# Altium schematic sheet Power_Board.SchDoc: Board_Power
size A4; Date: Not used; ApprovedBy: Not used; CheckedBy: Not used; Author: Not used; CompanyName: STMicroelectronics; DrawnBy: Not used; Engineer: Not used; Organization: Not used; Address1: Not used; Address2: Not used; Address3: Not used; Address4: Not used; DocumentNumber: Not used; Revision: Not used; SheetNumber: 15; SheetTotal: 17
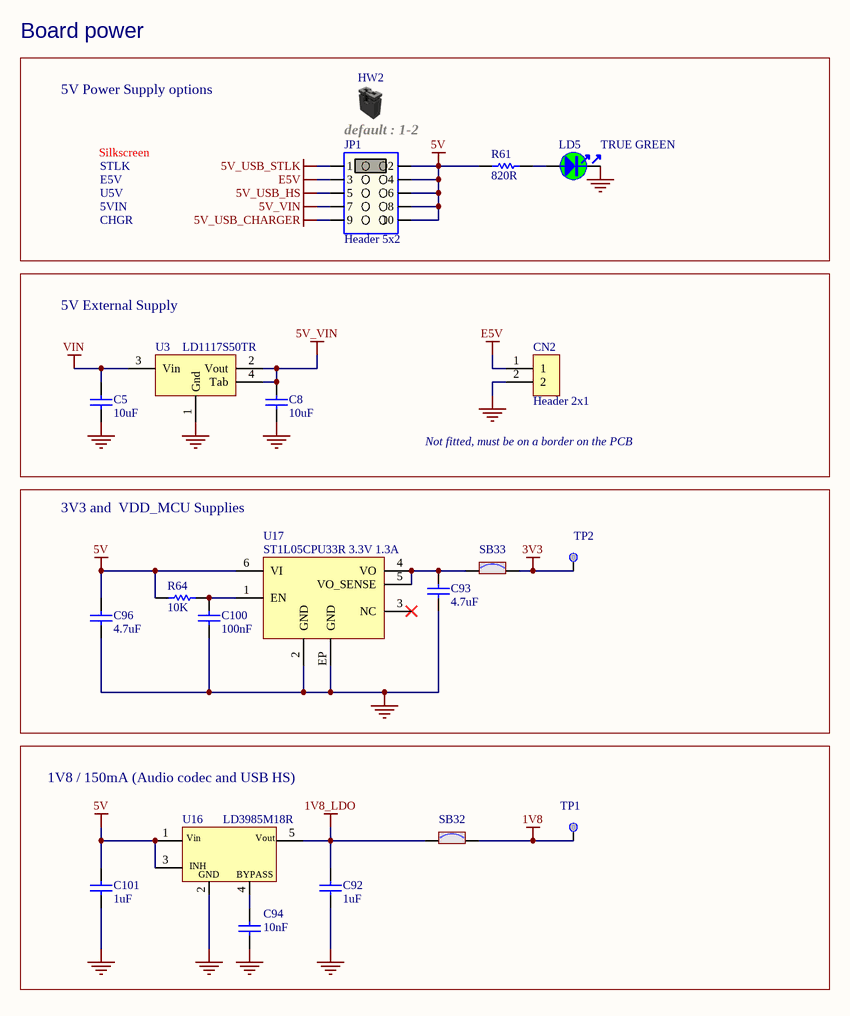
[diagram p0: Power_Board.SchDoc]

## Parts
C5  value 10uF  [C0805]  (hidden comment: Capacitor)
C8  value 10uF  [C0805]  (hidden comment: Capacitor)
C92  value 1uF  [C0402]  (hidden comment: Capacitor)
C93  value 4.7uF  [C0603]  (hidden comment: Capacitor)
C94  value 10nF  [C0402]  (hidden comment: Capacitor)
C96  value 4.7uF  [C0603]  (hidden comment: Capacitor)
C100  value 100nF  [C0402]  (hidden comment: Capacitor)
C101  value 1uF  [C0402]  (hidden comment: Capacitor)
CN2  Header 2x1  [CON_SAMTEC_TSW-102-07-G-S]
HW2  Shunt Black 2.54mm  (value not drawn)  (mechanical)
JP1  value Header 5x2  [CON_SAMTEC_TSM-105-01-L-DV]  (hidden comment: Jumper_Header 5x2 Fitted 1-2)
LD5  value TRUE GREEN  [LED_0603_VISHAY_VLMTG1300-GS08_GREEN_1A2K_H0P8]  (hidden comment: LED_green)
R61  value 820R  [R0603]  (hidden comment: Resistor)
R64  value 10K  [R0402]  (hidden comment: Resistor)
SB32  SB_ON  [SOLDER-BRIDGE_R0603-0R]  (value not drawn)
SB33  SB_ON  [SOLDER-BRIDGE_R0603-0R]  (value not drawn)
TP1  Test Point  [TP_SMD_2MM]  (value not drawn)  (no BOM)
TP2  Test Point  [TP_SMD_2MM]  (value not drawn)  (no BOM)
U3  LD1117S50TR  [REG_SOT223-TAB]
U16  LD3985M18R  [REG_SOT23-5L]
U17  value ST1L05CPU33R 3.3V 1.3A  [ICC_DFN6-EPAD_3X3_P095]  (hidden comment: ST1L05CPU33R)

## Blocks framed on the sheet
Board power: HW2 JP1 LD5 R61
5V External Supply: C5 C8 CN2 U3
3V3 and  VDD_MCU Supplies: C93 C96 C100 R64 SB33 TP2 U17
1V8 / 150mA (Audio codec and USB HS): C92 C94 C101 SB32 TP1 U16

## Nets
1V8: SB32.2 TP1.1
1V8_LDO: C92.2 SB32.1 U16.5(Vout)
3V3: SB33.2 TP2.1
5V: C96.2 C101.2 JP1.2 JP1.4 JP1.6 JP1.8 JP1.10 R61.1 R64.1 U16.1(Vin) U16.3(CE) U17.6(VI)
5V_USB_CHARGER: JP1.9
5V_USB_HS: JP1.5
5V_USB_STLK: JP1.1
5V_VIN: C8.2 JP1.7 U3.2(Vout) U3.4(Tab)
E5V: CN2.1 JP1.3
GND: C5.1 C8.1 C92.1 C93.1 C94.1 C96.1 C100.1 C101.1 CN2.2 LD5.2 U3.1(Gnd) U16.2(GND) U17.2(GND) U17.EP(GND)
VIN: C5.2 U3.3(Vin)
NetC93_2: C93.2 SB33.1 U17.4(VO) U17.5(VO_SENSE)
NetC94_2: C94.2 U16.4(BYPASS)
NetC100_2: C100.2 R64.2 U17.1(EN)
NetLD5_1: LD5.1 R61.2

Not connected (* = marked no-connect by the designer): U17 3(NC)*

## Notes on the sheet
- 5V Power Supply options
- Silkscreen
- default : 1-2
- STLK
- E5V
- U5V
- 5VIN
- CHGR
- Not fitted, must be on a border on the PCB

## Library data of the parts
C5 C8 = MCD-00014: Capacitor, MLCC, 10uF, 25V, X5R, 10%, 0805, T=0,85mm; Manufacturer_Part_Number: CC0805KRX5R8BB106; Manufacturer: YAGEO; Provided_By: SUBCO
C92 C101 = MCD-00095: Capacitor, MLCC, 1uF, 6V3, X5R, 10%, 0402, T=0,5mm; Manufacturer_Part_Number: GRM155R61E105KA12; Manufacturer: MURATA; Alternate_Manufacturer_Part_Number: GRM155R60J105KE19; Provided_By: SUBCO
C93 C96 = MCD-00009: Capacitor, MLCC, 4.7uF, 16V, X5R, 10%, 0603, T=0.8mm; Manufacturer_Part_Number: CC0603KRX5R7BB475; Manufacturer: YAGEO; Provided_By: SUBCO
C94 = MCD-00011: Capacitor, MLCC, 10nF, 16V, X7R, 10%, 0402, T=0.5mm; Manufacturer_Part_Number: CC0402KRX7R7BB103; Manufacturer: YAGEO; Provided_By: SUBCO
C100 = MCD-00006: Capacitor, MLCC, 100nF, 16V, X7R, 10%, 0402, T=0.5mm; Manufacturer_Part_Number: CC0402KRX7R7BB104; Manufacturer: YAGEO; Alternate_Manufacturer_Part_Number: GCM155R71C104KA55D; Alternate_Manufacturer: MURATA; Provided_By: SUBCO
CN2 = MCD-00032: Header, 2x1, 2,54mm, VR, TH, Height 5.84mm/2.54mm; Part_Type: Connector; Manufacturer_Part_Number: TSW-102-07-G-S; Manufacturer: SAMTEC; Alternate_Manufacturer_Part_Number: 313102S111116; Alternate_Manufacturer: JIUBABA; Part_Preference: Recommended
HW2 = MCD-00043: SHUNT 2.54mm BLACK; Part_Type: Mechanical; Manufacturer: SAMTEC; Alternate_Manufacturer_Part_Number: 316102S111A; Alternate_Manufacturer: JIUBABA; Value: SNT-100-BK-G; Provided_By: SUBCO
JP1 = MCD-01230: Header, 5x2, 2.54mm, VR, SMT, Height 5.84mm; Part_Type: Connector; Manufacturer_Part_Number: TSM-105-01-L-DV; Manufacturer: SAMTEC; Alternate_Manufacturer_Part_Number: PHFM25-1205G0B116T1; Alternate_Manufacturer: JIUBABA; Provided_By: SUBCO
LD5 = MCD-00589: LED Green, 0603 SMD, Fw Voltage = 2.8V - 3.6V; Part_Type: Display; Manufacturer_Part_Number: VLMTG1300-GS08; Manufacturer: VISHAY; Alternate_Manufacturer_Part_Number: LG Q396-PS-35; Alternate_Manufacturer: OSRAM OPTO SEMICONDUCTORS; Order_Code_RS: 7730452; Provided_By: SUBCO
R61 = MCD-00528: Resistor,820R,0603,1%,1/10W; Manufacturer_Part_Number: RC0603FR-07820RL; Manufacturer: YAGEO; BMS_Part_Number: 9129759; Provided_By: SUBCO
R64 = MCD-00053: Resistor,10K,0402,1%,1/16W; Manufacturer_Part_Number: RC0402FR-0710KL; Manufacturer: YAGEO; Provided_By: SUBCO
SB32 SB33 = MCD-00071: Solder Bridge ON; Part_Type: Mechanical; Manufacturer_Part_Number: RC0603JR-070RL; Manufacturer: YAGEO; Provided_By: SUBCO
TP1 TP2 = MCD-00177: Test Point 2mm; Part_Type: Mechanical
U3 = MCD-00088: IC REG LDO 5V 0.8A SOT223; Manufacturer: STMICROELECTRONICS; BMS_Part_Number: 9176133; Provided_By: SUBCO with ST control
U16 = MCD-00078: Ultra low drop-low noise BiCMOS voltage, regulators low ESR capacitors compatible; Manufacturer: STMICROELECTRONICS; Part_Type: IC; BMS_Part_Number: 9176159; Provided_By: SUBCO with ST control
U17 = MCD-01025: LDO, 3.3V, 1.3A, Very low quiescent current BiCMOS voltage regulator; Part_Type: IC; Manufacturer: STMICROELECTRONICS; BMS_Part_Number: 9176246; Provided_By: SUBCO with ST control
